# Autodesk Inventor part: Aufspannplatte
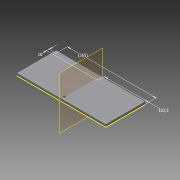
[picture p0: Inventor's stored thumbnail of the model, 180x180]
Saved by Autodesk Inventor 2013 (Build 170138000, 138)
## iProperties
Created: 2012-11
Part Number: Aufspannplatte
Material: Allgemein
Document SubType Name: Modeling
Designer: otto
Density: 1 g/cm^3
Author: otto
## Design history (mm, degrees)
sketch "Skizze1"
  geometry: L1 (-305, 0)-(0, 0) reference; L2 (-305, 0)-(-305, -50.5) reference; L3 (0, -50.5)-(-305, -50.5) reference; L4 (0, 0)-(0, -50.5) reference; L5 (-305, -101)-(0, -101) reference; L6 (0, -101)-(0, -50.5) reference; L7 (0, -50.5)-(-305, -50.5) reference; L8 (-305, -101)-(-305, -50.5) reference; L9 (-335, 30)-(30, 30); L10 (30, 30)-(30, -131); L11 (30, -131)-(-335, -131); L12 (-335, -131)-(-335, 30)
  constraints: 8 end point, 2 parallel, 1 horizontal, 1 perpendicular
  dimensions: "d0" = 30 distance between parallel lines of L5 L11; "d1" = 30 distance between parallel lines of L9 L1; "d2" = 30 distance from line of L12 L2.end; "d3" = 30 distance from line of L10 L3.start
extrude "Extrusion1" new body sketch "Skizze1" distance "d4" = 10; taper "d5" = 0 deg
workplane "Arbeitsebene1"
sketch "Skizze4"
  geometry: L1 (0, 10)-(-93.601, 44.068) reference; L2 (-93.601, 44.068)-(-95.311, 39.37) reference; L3 (-95.311, 39.37)-(8.57, 1.56) reference; L4 (8.57, 1.56)-(10.28, 6.258) reference; L5 (10.28, 6.258)-(0, 10) reference; 1 further point
revolve "Umdrehung1" sketch "Skizze4" stored, may be unused: angle "d12" = 90 deg
workplane "Arbeitsebene2"
mirror "Spiegeln1"
sketch "Skizze5"
  geometry: 2 further points
hole "Bohrung1" sketch "Skizze5" at (-152.5, -50.5) diameter "d13" = 3; stored, may be unused: countersink angle "d17" = 90 deg, drill point angle "d19" = 118 deg; dims "d14" = 6, "d15" = 4, "d16" = 2, "d18" = 32.5
node "Volumenkörper1"
node "Referenz1"
node "Referenz2"
